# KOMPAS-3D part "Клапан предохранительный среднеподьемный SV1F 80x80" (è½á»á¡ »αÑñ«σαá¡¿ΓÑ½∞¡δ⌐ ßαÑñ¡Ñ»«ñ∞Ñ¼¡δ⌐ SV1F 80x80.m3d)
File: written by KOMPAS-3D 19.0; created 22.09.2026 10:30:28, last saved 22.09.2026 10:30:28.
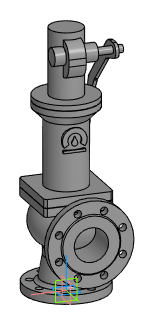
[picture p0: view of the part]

Document properties: Автор: Евгений; Полное имя файла: Z:\3.Личные\sachek\Dendor\_3D для проектировщиков\5.8 SV1F. Клапан предохранительный среднеподьемный\SV1F_STP\Клапан предохранительный среднеподьемный SV1F 80x80.m3d

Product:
- Part/product: Клапан предохранительный среднеподьемный SV1F 80x80
    Масса: 68.2874

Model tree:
1. Операция без истории:1  (labels: Клапан предохранительный среднеподьемный SV1F 80x80)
